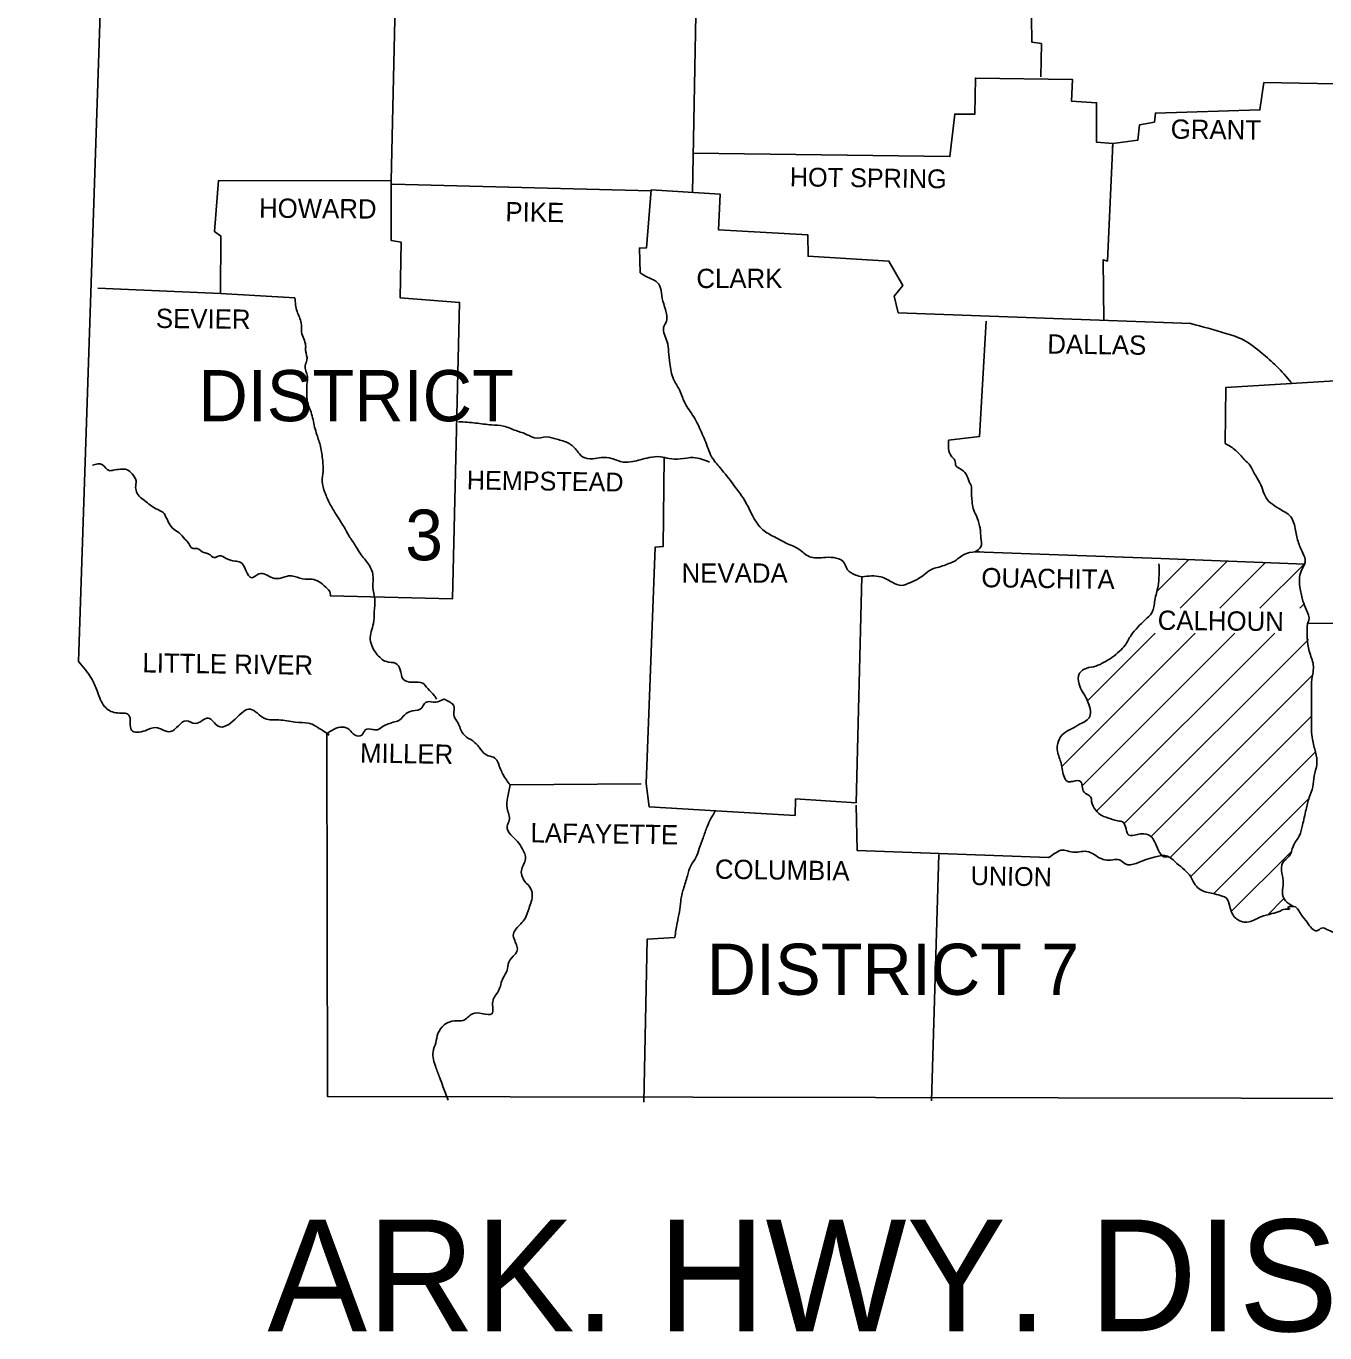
# Model space of a CAD drawing. Extents: x -492261 to -432772, y 1441225 to 1452922.
# Drawn here: x -457474.9 to -457172.7, y 1451793.9 to 1452098.1 of the extents above; entities that cross this region are included whole.
import ezdxf

# ---------------------------------------------------------------- set-up
doc = ezdxf.new("R2010")
doc.units = 0
doc.layers.add('Default', color=7, linetype='Continuous')

msp = doc.modelspace()

# ---------------------------------------------------------------- linework, layer by layer
at = {"layer": 'Default'}
for p, q in [((-457318.61, 1452124.91), (-457319.83, 1452059.34)), ((-457211.69, 1451966.51), (-457204.31, 1451973.88)), ((-457206.36, 1451962.56), (-457195.38, 1451973.53)), ((-457197.08, 1451962.56), (-457186.45, 1451973.18)), ((-457187.8, 1451962.56), (-457177.52, 1451972.84)), ((-457178.52, 1451962.56), (-457177.52, 1451963.56)), ((-457233.91, 1451925.73), (-457202.87, 1451956.77)), ((-457229.15, 1451921.2), (-457193.59, 1451956.77)), ((-457227.94, 1451940.98), (-457212.15, 1451956.77)), ((-457225.79, 1451915.29), (-457184.31, 1451956.77)), ((-457219.29, 1451912.5), (-457176.51, 1451955.29)), ((-457213.12, 1451909.4), (-457175.61, 1451946.91)), ((-457208.78, 1451904.45), (-457175.78, 1451937.46)), ((-457203.9, 1451900.06), (-457174.85, 1451929.11)), ((-457198.58, 1451896.1), (-457176.34, 1451918.35)), ((-457194.37, 1451892), (-457180.61, 1451905.75)), ((-457186.04, 1451891.13), (-457182.18, 1451895))]:
    msp.add_line(p, q, dxfattribs=at)
for points in [[(-457474.92, 1452406.92), (-457453.3, 1452233.39), (-457462.7, 1451950.12)], [(-457274.76, 1452128.98), (-457262.13, 1452128.04), (-457261.71, 1452114.88), (-457263.48, 1452114.26), (-457263.69, 1452107.26), (-457250.01, 1452106.32), (-457250.01, 1452100.58), (-457240.93, 1452100.06), (-457240.83, 1452094.31), (-457238.63, 1452094), (-457238.74, 1452086.27)], [(-457388.78, 1452113.42), (-457389.93, 1452062.05), (-457430.13, 1452062.16), (-457431.07, 1452050.25), (-457429.6, 1452049.21), (-457429.71, 1452035.84), (-457458.21, 1452037.1)], [(-457319.66, 1452068.52), (-457259.93, 1452067.69), (-457258.79, 1452077.61), (-457254.09, 1452077.61), (-457253.98, 1452085.96), (-457231.43, 1452085.65), (-457231.64, 1452080.64), (-457225.79, 1452080.22), (-457225.79, 1452071.03), (-457222.03, 1452070.72), (-457222.08, 1452069.76)], [(-457222.03, 1452070.72), (-457216.19, 1452071.55), (-457215.77, 1452075.1), (-457212.32, 1452075.73), (-457212.11, 1452077.82), (-457187.79, 1452078.55), (-457186.85, 1452084.92), (-457161.89, 1452084.5)], [(-457222.03, 1452070.72), (-457223.29, 1452043.36), (-457224.23, 1452043.68), (-457224.12, 1452029.48)], [(-457389.93, 1452062.05), (-457389.93, 1452048.16), (-457387.63, 1452047.75), (-457387.84, 1452034.8), (-457374.06, 1452033.76), (-457375.73, 1451964.74), (-457404.13, 1451965.47)], [(-457389.72, 1452061.32), (-457329.49, 1452059.74)], [(-457331.98, 1452040.65), (-457332.19, 1452046.39), (-457330.52, 1452046.49), (-457329.47, 1452059.96), (-457313.39, 1452058.92), (-457313.81, 1452050.67), (-457293.03, 1452049.52), (-457292.93, 1452044.51), (-457274.13, 1452043.36), (-457270.9, 1452037.72), (-457272.88, 1452035.22), (-457271.94, 1452031.36), (-457203.86, 1452028.85)], [(-457429.71, 1452035.84), (-457412.38, 1452034.8)], [(-457251.48, 1452029.37), (-457253.04, 1452002.54), (-457260.25, 1452001.7)], [(-457180.44, 1452014.86), (-457195.72, 1452013.92), (-457195.83, 1452000.87)], [(-457165.23, 1452015.8), (-457180.5, 1452014.86)], [(-457326.44, 1451997.74), (-457326.65, 1451976.96), (-457328.53, 1451976.75), (-457330.62, 1451921.73)], [(-457254.09, 1451975.7), (-457210.86, 1451974.14), (-457177.33, 1451972.83)], [(-457280.4, 1451969.86), (-457281.76, 1451917.24), (-457295.85, 1451918.18), (-457295.96, 1451914.31), (-457314.44, 1451915.39)], [(-457176.72, 1451959), (-457129.52, 1451959.1)], [(-457404.96, 1451933.31), (-457404.75, 1451848.85), (-457022.08, 1451848.22)], [(-457331.79, 1451921.71), (-457362.26, 1451921.41)], [(-457314.44, 1451915.39), (-457329.89, 1451916.3), (-457330.62, 1451921.73)], [(-457236.96, 1451904.5), (-457281.55, 1451906.17), (-457281.76, 1451916.71)], [(-457262.54, 1451905.23), (-457264.21, 1451847.91)], [(-457323.94, 1451885.91), (-457330.41, 1451885.5), (-457331.14, 1451847.59)]]:
    msp.add_lwpolyline(points, dxfattribs=at)
for points in [[(-457331.98, 1452040.65), (-457330.31, 1452039.6), (-457328.32, 1452038.66), (-457327.28, 1452037.1), (-457326.86, 1452034.7), (-457326.13, 1452032.09), (-457325.92, 1452029.37), (-457326.55, 1452027.91), (-457325.71, 1452024.57), (-457325.4, 1452022.27), (-457325.09, 1452019.56), (-457324.25, 1452015.9), (-457322.89, 1452013.4), (-457321.64, 1452010.37), (-457319.55, 1452007.13), (-457317.78, 1452003.58), (-457316.94, 1452001.7), (-457315.38, 1451997.84), (-457313.39, 1451995.23), (-457310.26, 1451991.26), (-457307.44, 1451987.19), (-457305.88, 1451984.16), (-457303.47, 1451980.82), (-457300.76, 1451979.15), (-457297.31, 1451977.38), (-457295.12, 1451976.33), (-457292.62, 1451974.56), (-457289.38, 1451974.35), (-457286.98, 1451974.35), (-457284.78, 1451973.41), (-457283.74, 1451971.53), (-457281.86, 1451970.28), (-457280.4, 1451969.86)], [(-457412.38, 1452034.8), (-457411.85, 1452031.67), (-457410.91, 1452028.95), (-457410.81, 1452026.87), (-457409.87, 1452023.73), (-457409.87, 1452022.58), (-457409.56, 1452020.29), (-457409.97, 1452019.03), (-457409.45, 1452016.53), (-457409.56, 1452014.65), (-457409.56, 1452013.08), (-457409.45, 1452010.47), (-457408.62, 1452008.18), (-457407.78, 1452004.73), (-457407.26, 1452002.96), (-457406.42, 1452000.24), (-457405.9, 1451996.9), (-457405.8, 1451994.39), (-457406.01, 1451992.1), (-457405.38, 1451989.49), (-457404.23, 1451986.88), (-457402.77, 1451984.37), (-457400.99, 1451981.55), (-457399.74, 1451979.36), (-457398.18, 1451976.96), (-457396.92, 1451974.97), (-457395.04, 1451972.47), (-457394.21, 1451970.38), (-457394.21, 1451967.46), (-457393.79, 1451964.74), (-457393.89, 1451961.71), (-457394.1, 1451959), (-457394.83, 1451955.24), (-457394.31, 1451953.47), (-457392.33, 1451950.86), (-457391.08, 1451950.12), (-457388.88, 1451949.71), (-457387.84, 1451948.25), (-457387.21, 1451946.05), (-457385.02, 1451945.32), (-457382.62, 1451945.11), (-457381.47, 1451943.86), (-457379.9, 1451942.19), (-457379.38, 1451941.35)], [(-457203.86, 1452028.85), (-457195.72, 1452026.55), (-457191.54, 1452024.99), (-457187.37, 1452021.96), (-457183.92, 1452018.93), (-457180.48, 1452015.07)], [(-457374.27, 1452005.98), (-457370.3, 1452005.67), (-457366.64, 1452005.25), (-457363.82, 1452004.94), (-457360.9, 1452003.9), (-457358.29, 1452002.96), (-457356.62, 1452002.22), (-457353.8, 1452002.43), (-457351.4, 1452001.91), (-457348.68, 1452000.97), (-457346.7, 1451999.2), (-457345.45, 1451997.84), (-457343.05, 1451997.32), (-457341.06, 1451997.63), (-457338.66, 1451997.42), (-457335.95, 1451996.59), (-457333.75, 1451996.69), (-457331.98, 1451997.11), (-457329.89, 1451997.63), (-457327.28, 1451997.84), (-457325.3, 1451997.42), (-457322.69, 1451997.32), (-457319.66, 1451997.63), (-457315.9, 1451996.59)], [(-457260.25, 1452001.7), (-457260.25, 1451999.72), (-457259.52, 1451997.84), (-457258.79, 1451997), (-457258.47, 1451995.65), (-457257.53, 1451995.02), (-457256.18, 1451993.77), (-457255.44, 1451991.99), (-457254.92, 1451990.84), (-457254.92, 1451989.38), (-457254.82, 1451987.92), (-457254.61, 1451986.15), (-457253.36, 1451983.01), (-457253.04, 1451981.76), (-457252.83, 1451980.72), (-457252.73, 1451978.94), (-457252.73, 1451976.85), (-457254.09, 1451975.7)], [(-457195.83, 1452000.87), (-457193.42, 1451999.3), (-457191.44, 1451997.21), (-457189.98, 1451995.65), (-457189.04, 1451993.87), (-457187.79, 1451991.78), (-457186.01, 1451987.82), (-457184.44, 1451986.46), (-457182.25, 1451985.1), (-457180.89, 1451984.16), (-457179.54, 1451981.13), (-457178.91, 1451978.11), (-457177.76, 1451975.39), (-457177.24, 1451973.3), (-457178.18, 1451971.22), (-457178.39, 1451967.04), (-457177.76, 1451964.22), (-457176.93, 1451962.13), (-457176.4, 1451959.73), (-457176.72, 1451959)], [(-457459.47, 1451995.86), (-457457.17, 1451995.96), (-457455.6, 1451994.6), (-457454.66, 1451994.71), (-457452.99, 1451994.92), (-457451.43, 1451994.81), (-457450.28, 1451993.87), (-457449.34, 1451992.2), (-457449.44, 1451990.64), (-457449.34, 1451990.01), (-457448.61, 1451988.65), (-457447.35, 1451987.61), (-457446, 1451986.56), (-457444.74, 1451985.73), (-457442.65, 1451984.37), (-457442.45, 1451983.95), (-457441.61, 1451982.28), (-457440.57, 1451980.93), (-457439.31, 1451980.09), (-457437.96, 1451978.63), (-457437.33, 1451978), (-457436.29, 1451976.54), (-457435.14, 1451976.44), (-457433.57, 1451975.5), (-457432.42, 1451975.18), (-457431.17, 1451974.35), (-457429.92, 1451974.77), (-457428.35, 1451974.14), (-457426.26, 1451973.51), (-457425.11, 1451973.3), (-457423.76, 1451971.32), (-457422.4, 1451969.65), (-457420.73, 1451970.59), (-457417.6, 1451969.65), (-457415.61, 1451969.54), (-457413.84, 1451970.07), (-457412.48, 1451969.96), (-457409.97, 1451969.34), (-457408.41, 1451969.34), (-457406.74, 1451968.71), (-457405.17, 1451967.46), (-457404.13, 1451966.1), (-457404.13, 1451965.47)], [(-457258.79, 1451973.51), (-457256.07, 1451975.29), (-457253.04, 1451975.7)], [(-457258.79, 1451973.51), (-457259.54, 1451973.2), (-457260.87, 1451972.68), (-457262.44, 1451972.15), (-457263.9, 1451971.74), (-457265.78, 1451970.48), (-457267.24, 1451969.44), (-457269.23, 1451968.5), (-457271.11, 1451967.87), (-457273.4, 1451968.61), (-457274.66, 1451969.34), (-457276.01, 1451969.86), (-457280.4, 1451969.86)], [(-457211.28, 1451972.89), (-457211.49, 1451967.67), (-457212.22, 1451964.43), (-457212.95, 1451961.51), (-457214.51, 1451959.83), (-457216.19, 1451958.16), (-457217.75, 1451956.28), (-457219.11, 1451953.99), (-457220.47, 1451952.53), (-457222.24, 1451951.06), (-457224.02, 1451950.02), (-457226, 1451949.08), (-457228.19, 1451948.56), (-457229.76, 1451947.41), (-457229.86, 1451944.9), (-457228.09, 1451941.35), (-457227.46, 1451939.68), (-457227.25, 1451937.7), (-457227.98, 1451936.55), (-457229.65, 1451935.61), (-457231.64, 1451934.46), (-457233.41, 1451933.42), (-457234.67, 1451931.64), (-457234.88, 1451929.24), (-457234.04, 1451926.42), (-457233.73, 1451924.75), (-457232.37, 1451922.14), (-457231.33, 1451922.25), (-457229.45, 1451922.14), (-457229.24, 1451921.62), (-457229.13, 1451921.1), (-457228.71, 1451919.74), (-457227.15, 1451918.59), (-457226.94, 1451917.55), (-457226, 1451915.57), (-457224.43, 1451914.21), (-457223.29, 1451913.79), (-457220.88, 1451913.06), (-457219.63, 1451912.75), (-457218.27, 1451909.72), (-457216.6, 1451909.82), (-457215.35, 1451910.03), (-457213.26, 1451909.51), (-457212.32, 1451908.26), (-457211.38, 1451906.17), (-457210.13, 1451904.71), (-457209.29, 1451904.71)], [(-457176.72, 1451959), (-457176.3, 1451952.53), (-457175.36, 1451949.39), (-457175.67, 1451946.05), (-457175.78, 1451942.82), (-457175.78, 1451939.89), (-457175.78, 1451937.07), (-457175.78, 1451934.15), (-457175.57, 1451932.06), (-457174.84, 1451929.03), (-457174.53, 1451926.21), (-457175.15, 1451923.5), (-457175.46, 1451920.99), (-457176.3, 1451918.49), (-457177.03, 1451915.67), (-457177.87, 1451912.02), (-457178.6, 1451909.61), (-457180.06, 1451907.11), (-457181, 1451904.81), (-457182.46, 1451903.35), (-457182.67, 1451900.84), (-457182.36, 1451898.55), (-457182.56, 1451896.46), (-457181.83, 1451894.47), (-457179.95, 1451893.12)], [(-457462.7, 1451950.12), (-457459.67, 1451946.16), (-457458.42, 1451943.34), (-457456.65, 1451939.68), (-457454.04, 1451938.22), (-457451.01, 1451937.7), (-457450.38, 1451934.15), (-457447.25, 1451934.05), (-457444.74, 1451934.78), (-457441.3, 1451933.84), (-457437.64, 1451936.34), (-457435.55, 1451935.72), (-457432.53, 1451936.97), (-457430.23, 1451935.09), (-457426.26, 1451936.76), (-457422.71, 1451939.06), (-457419.37, 1451936.86), (-457416.13, 1451936.55), (-457412.27, 1451936.03), (-457409.24, 1451935.82), (-457406.53, 1451934.46), (-457404.54, 1451933.11), (-457404.96, 1451933.31)], [(-457404.96, 1451933.31), (-457401.31, 1451934.88), (-457399.74, 1451934.36), (-457398.38, 1451933), (-457396.82, 1451933), (-457395.98, 1451934.25), (-457394.42, 1451934.36), (-457393.16, 1451934.25), (-457391.81, 1451935.09), (-457390.66, 1451935.61), (-457389.09, 1451936.13), (-457387.94, 1451936.55), (-457386.9, 1451937.7), (-457385.02, 1451938.64), (-457382.83, 1451939.37), (-457382.2, 1451940.41), (-457381.16, 1451940.83), (-457379.07, 1451940.73), (-457377.71, 1451941.35), (-457376.56, 1451940.83), (-457375.52, 1451940.1), (-457375.31, 1451937.39), (-457374.47, 1451935.92), (-457373.22, 1451933.31), (-457371.45, 1451931.96), (-457369.78, 1451930.6), (-457369.15, 1451929.76), (-457367.37, 1451928.2), (-457365.81, 1451927.68), (-457365.08, 1451926.53), (-457363.93, 1451923.81), (-457362.26, 1451921.41)], [(-457362.26, 1451921.41), (-457362.88, 1451918.38), (-457362.99, 1451915.98), (-457362.47, 1451913.16), (-457362.99, 1451911.81), (-457362.15, 1451909.82), (-457360.59, 1451908.26), (-457359.44, 1451906.59), (-457358.71, 1451904.18), (-457359.65, 1451901.47), (-457358.6, 1451898.65), (-457357.66, 1451897.61), (-457357.14, 1451895.94), (-457357.87, 1451892.7), (-457358.81, 1451890.3), (-457360.9, 1451887.9), (-457361.53, 1451886.75), (-457361.21, 1451885.18), (-457360.69, 1451882.68), (-457361.21, 1451881.95), (-457362.57, 1451880.17), (-457362.99, 1451878.19), (-457363.93, 1451876.52), (-457364.97, 1451873.49), (-457366.33, 1451870.98), (-457366.54, 1451868.16), (-457368.63, 1451868.16), (-457371.03, 1451868.16), (-457373.22, 1451866.6), (-457375.2, 1451866.49), (-457377.61, 1451865.55), (-457379.07, 1451863.57), (-457379.59, 1451861.38), (-457380.22, 1451859.29), (-457379.59, 1451855.74), (-457378.65, 1451853.23), (-457377.92, 1451851.25), (-457376.67, 1451848.01)], [(-457323.94, 1451885.91), (-457323.42, 1451889.25), (-457322.89, 1451891.86), (-457322.58, 1451894.37), (-457321.95, 1451897.19), (-457321.02, 1451900.22), (-457320.18, 1451902.72), (-457319.03, 1451904.5), (-457318.3, 1451906.59), (-457317.36, 1451909.09), (-457316.42, 1451911.7), (-457314.55, 1451915.38)], [(-457236.96, 1451904.5), (-457235.29, 1451905.65), (-457233.73, 1451906.27), (-457232.16, 1451905.96), (-457230.49, 1451905.75), (-457229.03, 1451905.96), (-457227.15, 1451905.65), (-457225.58, 1451904.71), (-457223.81, 1451903.98), (-457222.03, 1451903.98), (-457220.47, 1451903.98), (-457219.11, 1451903.04), (-457216.6, 1451903.14), (-457214.51, 1451903.98), (-457212.43, 1451904.6), (-457209.61, 1451904.92), (-457207.1, 1451903.14), (-457205.33, 1451901.68), (-457203.86, 1451900.01), (-457202.82, 1451898.13), (-457201.67, 1451897.08), (-457199.79, 1451896.35), (-457198.33, 1451896.04), (-457196.56, 1451895.52), (-457195.62, 1451895.1), (-457194.78, 1451893.12), (-457193.42, 1451890.4), (-457190.81, 1451889.46), (-457187.58, 1451890.72), (-457184.97, 1451891.45), (-457183.09, 1451892.07), (-457181.94, 1451892.49), (-457180.89, 1451892.6), (-457181.21, 1451892.8), (-457179.95, 1451893.12), (-457178.81, 1451892.28), (-457178.08, 1451891.13), (-457176.82, 1451889.46), (-457175.67, 1451888), (-457174.53, 1451887.48), (-457173.38, 1451888.11), (-457171.81, 1451887.58), (-457170.45, 1451887.06), (-457168.89, 1451886.64), (-457167.53, 1451886.54), (-457165.75, 1451886.12), (-457164.4, 1451885.39), (-457163.14, 1451884.66), (-457161.89, 1451883.3), (-457160.64, 1451881.21), (-457160.22, 1451879.54), (-457158.76, 1451877.87), (-457157.4, 1451877.87), (-457155.42, 1451875.16), (-457154.69, 1451874.11), (-457153.12, 1451872.24), (-457151.97, 1451872.24), (-457149.78, 1451871.82)]]:
    msp.add_spline(points, degree=3, dxfattribs=at)

# ---------------------------------------------------------------- texts
for s, height, rotation, p in [('GRANT', 4.49, 359.4032, (-457208.56, 1452071.87)), ('HOT SPRING', 4.386, 359.2216, (-457297.21, 1452060.8)), ('HOWARD', 4.49, 359.5145, (-457420.73, 1452053.49)), ('PIKE', 4.489, 359.0452, (-457363.41, 1452052.65)), ('SEVIER', 4.49, 359.4271, (-457444.74, 1452027.81)), ('DALLAS', 4.489, 359.2462, (-457237.28, 1452021.85)), ('HEMPSTEAD', 4.384, 359.1885, (-457372.39, 1451990.22)), ('OUACHITA', 4.49, 359.2043, (-457252.63, 1451967.46)), ('CALHOUN', 4.49, 359.3634, (-457211.59, 1451957.54)), ('LITTLE RIVER', 4.4903, 359.1697, (-457447.88, 1451947.62)), ('MILLER', 4.489, 359.132, (-457397.24, 1451926.63)), ('LAFAYETTE', 4.489, 359.1839, (-457357.56, 1451908.05)), ('COLUMBIA', 4.489, 359.2125, (-457314.65, 1451899.59)), ('UNION', 4.386, 358.9584, (-457255.13, 1451898.13))]:
    msp.add_text(s, height=height, rotation=rotation, dxfattribs=at).set_placement(p)
for s, height, p in [('CLARK', 4.49, (-457318.93, 1452037.1)), ('DISTRICT', 11.903, (-457434.82, 1452006.09)), ('3', 11.8, (-457386.69, 1451973.72)), ('NEVADA', 4.49, (-457322.37, 1451968.5)), ('DISTRICT 7', 11.903, (-457316.53, 1451872.55)), ('  ARK. HWY. DIST. NO. 7', 26, (-457438.08, 1451794.23))]:
    msp.add_text(s, height=height, dxfattribs=at).set_placement(p)

doc.saveas('drawing.dxf')
